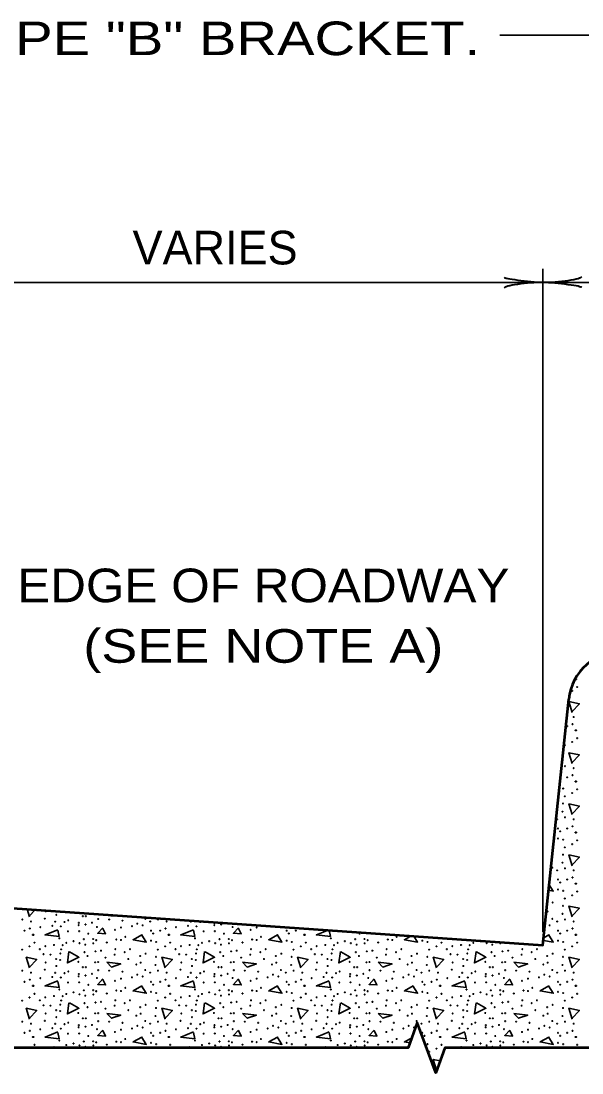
# Model space of a CAD drawing. Extents: x -105 to 751, y -65 to 479.
# Drawn here: x 7.8 to 57.8, y -3.9 to 90 of the extents above; entities that cross this region are included whole.
import ezdxf
from ezdxf.enums import TextEntityAlignment as Align

# ---------------------------------------------------------------- set-up
doc = ezdxf.new("R2010")
doc.units = 0
doc.header["$LTSCALE"] = 1.2
doc.layers.add('1', color=7, linetype='Continuous', lineweight=35)

msp = doc.modelspace()

# ---------------------------------------------------------------- linework, layer by layer
at = {"layer": '1'}
for p, q in [((54.365, 8.704), (54.365, 67.839)), ((8.582, 10.032), (8.375, 10.72)), ((9.108, 10.669), (8.558, 10.08)), ((54.902, 8.424), (54.435, 8.169)), ((44.957, -3.481), (44.846, -3.6))]:
    msp.add_line(p, q, dxfattribs=at)
for points in [[(50.512, 88.687), (79.059, 88.687), (79.059, 72.823)], [(-1.897, 66.639), (54.365, 66.639), (105.725, 66.639)], [(56.966, 28.272), (56.678, 29.232), (57.614, 29.04), (56.942, 28.32)], [(56.966, 23.712), (56.678, 24.672), (57.614, 24.48), (56.942, 23.76)], [(56.966, 19.152), (56.678, 20.112), (57.614, 19.92), (56.942, 19.2)], [(56.966, 14.592), (56.678, 15.552), (57.614, 15.36), (56.942, 14.64)], [(54.881, 12.41), (55.286, 12.336), (54.931, 12.888)], [(56.966, 10.032), (56.678, 10.992), (57.614, 10.8), (56.942, 10.08)], [(16.116, 10.179), (15.902, 10.104), (15.805, 10.201)], [(11.102, 8.88), (9.974, 8.424), (11.222, 8.28), (11.102, 8.832)], [(15.134, 9.048), (14.678, 8.568), (15.374, 8.52), (15.134, 9)], [(18.614, 8.424), (17.822, 7.992), (18.998, 7.776), (18.566, 8.448)], [(23.198, 8.88), (22.07, 8.424), (23.318, 8.28), (23.198, 8.832)], [(27.23, 9.048), (26.774, 8.568), (27.47, 8.52), (27.23, 9)], [(30.71, 8.424), (29.918, 7.992), (31.094, 7.776), (30.662, 8.448)], [(35.206, 8.844), (34.166, 8.424), (35.414, 8.28), (35.294, 8.832)], [(38.888, 8.587), (38.87, 8.568), (39.566, 8.52), (39.556, 8.54)], [(54.411, 7.936), (55.286, 7.776), (54.854, 8.448)], [(42.626, 8.325), (42.014, 7.992), (43.19, 7.776), (42.846, 8.31)], [(12.158, 6.912), (12.998, 6.432), (11.966, 5.928), (12.11, 6.936)], [(24.254, 6.912), (25.094, 6.432), (24.062, 5.928), (24.206, 6.936)], [(36.35, 6.912), (37.19, 6.432), (36.158, 5.928), (36.302, 6.936)], [(48.446, 6.912), (49.286, 6.432), (48.254, 5.928), (48.398, 6.936)], [(8.582, 5.472), (8.294, 6.432), (9.23, 6.24), (8.558, 5.52)], [(20.678, 5.472), (20.39, 6.432), (21.326, 6.24), (20.654, 5.52)], [(32.774, 5.472), (32.486, 6.432), (33.422, 6.24), (32.75, 5.52)], [(44.87, 5.472), (44.582, 6.432), (45.518, 6.24), (44.846, 5.52)], [(56.966, 5.472), (56.678, 6.432), (57.614, 6.24), (56.942, 5.52)], [(11.102, 4.32), (9.974, 3.864), (11.222, 3.72), (11.102, 4.272)], [(15.134, 4.488), (14.678, 4.008), (15.374, 3.96), (15.134, 4.44)], [(18.614, 3.864), (17.822, 3.432), (18.998, 3.216), (18.566, 3.888)], [(23.198, 4.32), (22.07, 3.864), (23.318, 3.72), (23.198, 4.272)], [(27.23, 4.488), (26.774, 4.008), (27.47, 3.96), (27.23, 4.44)], [(30.71, 3.864), (29.918, 3.432), (31.094, 3.216), (30.662, 3.888)], [(35.294, 4.32), (34.166, 3.864), (35.414, 3.72), (35.294, 4.272)], [(39.326, 4.488), (38.87, 4.008), (39.566, 3.96), (39.326, 4.44)], [(42.806, 3.864), (42.014, 3.432), (43.19, 3.216), (42.758, 3.888)], [(47.39, 4.32), (46.262, 3.864), (47.51, 3.72), (47.39, 4.272)], [(51.422, 4.488), (50.966, 4.008), (51.662, 3.96), (51.422, 4.44)], [(54.902, 3.864), (54.11, 3.432), (55.286, 3.216), (54.854, 3.888)], [(12.158, 2.352), (12.998, 1.872), (11.966, 1.368), (12.11, 2.376)], [(24.254, 2.352), (25.094, 1.872), (24.062, 1.368), (24.206, 2.376)], [(36.35, 2.352), (37.19, 1.872), (36.158, 1.368), (36.302, 2.376)], [(48.446, 2.352), (49.286, 1.872), (48.254, 1.368), (48.398, 2.376)], [(8.582, 0.912), (8.294, 1.872), (9.23, 1.68), (8.558, 0.96)], [(20.678, 0.912), (20.39, 1.872), (21.326, 1.68), (20.654, 0.96)], [(32.774, 0.912), (32.486, 1.872), (33.422, 1.68), (32.75, 0.96)], [(44.87, 0.912), (44.582, 1.872), (45.518, 1.68), (44.846, 0.96)], [(56.966, 0.912), (56.678, 1.872), (57.614, 1.68), (56.942, 0.96)], [(11.102, -0.24), (9.974, -0.696), (11.222, -0.84), (11.102, -0.288)], [(15.134, -0.072), (14.678, -0.552), (15.374, -0.6), (15.134, -0.12)], [(18.614, -0.696), (17.822, -1.128), (18.998, -1.344), (18.566, -0.672)], [(23.198, -0.24), (22.07, -0.696), (23.318, -0.84), (23.198, -0.288)], [(27.23, -0.072), (26.774, -0.552), (27.47, -0.6), (27.23, -0.12)], [(30.71, -0.696), (29.918, -1.128), (31.094, -1.344), (30.662, -0.672)], [(35.294, -0.24), (34.166, -0.696), (35.414, -0.84), (35.294, -0.288)], [(39.326, -0.072), (38.87, -0.552), (39.566, -0.6), (39.326, -0.12)], [(42.658, -0.777), (42.014, -1.128), (42.498, -1.217)], [(47.39, -0.24), (46.262, -0.696), (47.51, -0.84), (47.39, -0.288)], [(51.422, -0.072), (50.966, -0.552), (51.662, -0.6), (51.422, -0.12)], [(54.902, -0.696), (54.11, -1.128), (55.286, -1.344), (54.854, -0.672)], [(44.87, -3.648), (44.582, -2.688), (45.2, -2.815)]]:
    msp.add_lwpolyline(points, dxfattribs=at)
at = {"layer": '1', "lineweight": 53}
for points in [[(-24.539, 11.439), (-1.897, 11.439), (54.365, 7.504), (56.673, 29.462)], [(120.627, -1.64), (45.627, -1.64), (44.806, -3.895), (43.165, 0.615), (42.344, -1.64), (-3.856, -1.64), (-4.677, -3.895), (-6.318, 0.615), (-7.139, -1.64), (-24.539, -1.64), (-24.539, 3.258), (-26.794, 4.079), (-22.284, 5.72), (-24.539, 6.541), (-24.539, 11.439)]]:
    msp.add_lwpolyline(points, dxfattribs=at)
at = {"layer": '1'}
for points in [[(15.47, 5.976), (16.718, 5.832), (15.902, 5.544)], [(27.566, 5.976), (28.814, 5.832), (27.998, 5.544)], [(39.662, 5.976), (40.91, 5.832), (40.094, 5.544)], [(51.758, 5.976), (53.006, 5.832), (52.19, 5.544)], [(15.47, 1.416), (16.718, 1.272), (15.902, 0.984)], [(27.566, 1.416), (28.814, 1.272), (27.998, 0.984)], [(39.662, 1.416), (40.91, 1.272), (40.094, 0.984)], [(51.758, 1.416), (53.006, 1.272), (52.19, 0.984)]]:
    msp.add_lwpolyline(points, close=True, dxfattribs=at)
for centre in [(57.334, 31.232), (56.968, 30.198), (57.413, 30.532), (57, 27.229), (57.111, 27.86), (56.523, 27.038), (57.27, 26.672), (57.334, 26.672), (56.316, 25.352), (56.968, 25.638), (57.413, 25.972), (56.332, 23.475), (57, 22.669), (57.111, 23.3), (56.523, 22.478), (57.27, 22.112), (57.334, 22.112), (56.173, 21.476), (56.316, 20.792), (56.968, 21.078), (57.413, 21.412), (56.157, 20.14), (55.632, 18.74), (56.109, 19.424), (56.332, 18.915), (57.111, 18.74), (55.711, 17.918), (56.523, 17.918), (57, 18.109), (55.711, 17.027), (55.902, 17.664), (56.173, 16.916), (57.27, 17.552), (57.334, 17.552), (56.316, 16.232), (56.968, 16.518), (57.413, 16.852), (56.157, 15.58), (55.203, 14.418), (55.632, 14.18), (56.109, 14.864), (56.332, 14.355), (57.111, 14.18), (55.711, 13.358), (56.523, 13.358), (57, 13.549), (55.711, 12.467), (55.902, 13.104), (56.173, 12.356), (57.27, 12.992), (57.334, 12.992), (57.413, 12.292), (55.234, 11.306), (56.316, 11.672), (56.968, 11.958), (10.031, 10.526), (54.789, 10.511), (56.109, 10.304), (56.157, 11.02), (7.948, 9.795), (8.727, 9.62), (9.952, 9.874), (10.874, 9.604), (10.985, 10.208), (11.717, 9.572), (12.051, 9.715), (12.989, 9.492), (13.339, 10.097), (13.578, 9.355), (13.609, 10.097), (14.166, 9.508), (14.716, 9.842), (15.686, 9.795), (16.879, 9.699), (18.199, 9.429), (18.915, 9.858), (19.344, 9.62), (20.044, 9.795), (20.823, 9.62), (22.97, 9.604), (23.813, 9.572), (25.085, 9.492), (25.674, 9.355), (55.203, 9.858), (55.632, 9.62), (56.332, 9.795), (57.111, 9.62), (8.139, 8.798), (8.616, 8.989), (8.886, 8.432), (8.95, 8.432), (9.554, 9.116), (10.62, 9.228), (11.383, 9.18), (12.019, 8.735), (12.973, 9.291), (13.021, 8.75), (13.832, 8.528), (14.605, 9.132), (16.211, 8.878), (16.752, 9.084), (17.722, 9.196), (18.676, 9.275), (19.423, 8.798), (19.614, 8.544), (20.235, 8.798), (20.712, 8.989), (20.982, 8.432), (21.046, 8.432), (21.65, 9.116), (22.716, 9.228), (23.479, 9.18), (24.115, 8.735), (25.069, 9.291), (25.117, 8.75), (25.928, 8.528), (26.701, 9.132), (28.307, 8.878), (28.848, 9.084), (31.519, 8.798), (31.71, 8.544), (32.331, 8.798), (33.078, 8.432), (33.142, 8.432), (36.211, 8.735), (38.024, 8.528), (54.964, 9.275), (55.711, 8.798), (55.902, 8.544), (56.523, 8.798), (57, 8.989), (57.27, 8.432), (57.334, 8.432), (9.029, 7.732), (10.779, 7.526), (11.256, 8.114), (11.542, 7.51), (11.876, 7.716), (12.512, 7.86), (13.053, 7.685), (13.434, 8.035), (13.562, 7.557), (14.262, 8.05), (14.277, 7.669), (14.541, 7.955), (15.479, 7.748), (16.338, 8.019), (16.752, 7.971), (17.133, 8.257), (19.423, 7.907), (19.885, 7.796), (21.125, 7.732), (22.875, 7.526), (23.352, 8.114), (23.638, 7.51), (23.972, 7.716), (24.608, 7.86), (25.149, 7.685), (25.53, 8.035), (25.658, 7.557), (26.358, 8.05), (26.373, 7.669), (26.637, 7.955), (27.575, 7.748), (28.434, 8.019), (28.848, 7.971), (29.229, 8.257), (31.519, 7.907), (31.981, 7.796), (33.221, 7.732), (34.971, 7.526), (35.448, 8.114), (35.734, 7.51), (36.068, 7.716), (36.704, 7.86), (37.245, 7.685), (37.626, 8.035), (37.754, 7.557), (38.454, 8.05), (38.469, 7.669), (38.733, 7.955), (39.671, 7.748), (40.53, 8.019), (40.944, 7.971), (41.325, 8.257), (43.615, 7.907), (44.077, 7.796), (45.317, 7.732), (47.067, 7.526), (47.83, 7.51), (48.164, 7.716), (48.8, 7.86), (49.341, 7.685), (49.85, 7.557), (50.565, 7.669), (55.711, 7.907), (56.173, 7.796), (57.413, 7.732), (7.932, 7.112), (8.584, 7.398), (9.506, 7.144), (9.84, 6.698), (9.999, 7.414), (10.46, 6.666), (11.335, 6.762), (11.415, 7.128), (13.498, 6.889), (13.768, 6.539), (14.468, 6.953), (14.97, 7.016), (16.179, 6.666), (16.243, 7.144), (17.07, 6.889), (17.547, 7.144), (18.453, 6.539), (18.946, 6.746), (20.028, 7.112), (20.68, 7.398), (21.602, 7.144), (21.936, 6.698), (22.095, 7.414), (22.556, 6.666), (23.431, 6.762), (23.511, 7.128), (25.594, 6.889), (25.864, 6.539), (26.564, 6.953), (27.066, 7.016), (28.275, 6.666), (28.339, 7.144), (29.166, 6.889), (29.643, 7.144), (30.549, 6.539), (31.042, 6.746), (32.124, 7.112), (32.776, 7.398), (33.698, 7.144), (34.032, 6.698), (34.191, 7.414), (34.652, 6.666), (35.527, 6.762), (35.607, 7.128), (37.69, 6.889), (37.96, 6.539), (38.66, 6.953), (39.162, 7.016), (40.371, 6.666), (40.435, 7.144), (41.262, 6.889), (41.739, 7.144), (42.645, 6.539), (43.138, 6.746), (44.22, 7.112), (44.872, 7.398), (45.794, 7.144), (46.128, 6.698), (46.287, 7.414), (46.748, 6.666), (47.623, 6.762), (47.703, 7.128), (49.786, 6.889), (50.056, 6.539), (50.756, 6.953), (51.258, 7.016), (52.467, 6.666), (52.531, 7.144), (53.358, 6.889), (53.835, 7.144), (54.741, 6.539), (55.234, 6.746), (56.316, 7.112), (56.968, 7.398), (10.031, 5.966), (10.969, 6.269), (10.985, 5.648), (11.319, 6.189), (12.941, 6.014), (14.445, 5.98), (14.716, 5.998), (15.368, 6.396), (17.404, 6.269), (18.119, 5.776), (18.501, 5.951), (19.821, 5.744), (19.869, 6.46), (22.127, 5.966), (23.065, 6.269), (23.081, 5.648), (23.415, 6.189), (25.037, 6.014), (26.541, 5.98), (26.812, 5.998), (27.464, 6.396), (29.5, 6.269), (30.215, 5.776), (30.597, 5.951), (31.917, 5.744), (31.965, 6.46), (34.223, 5.966), (35.161, 6.269), (35.177, 5.648), (35.511, 6.189), (37.133, 6.014), (38.637, 5.98), (38.908, 5.998), (39.56, 6.396), (41.596, 6.269), (42.311, 5.776), (42.693, 5.951), (44.013, 5.744), (44.061, 6.46), (46.319, 5.966), (47.257, 6.269), (47.273, 5.648), (47.607, 6.189), (49.229, 6.014), (50.733, 5.98), (51.004, 5.998), (51.656, 6.396), (53.692, 6.269), (54.407, 5.776), (54.789, 5.951), (56.109, 5.744), (56.157, 6.46), (7.948, 5.235), (8.727, 5.06), (9.952, 5.314), (10.62, 4.668), (10.874, 5.044), (11.717, 5.012), (12.051, 5.155), (12.973, 4.731), (12.989, 4.932), (13.339, 5.537), (13.578, 4.795), (13.609, 5.537), (14.166, 4.948), (14.716, 5.282), (15.686, 5.235), (16.879, 5.139), (18.199, 4.869), (18.676, 4.715), (18.915, 5.298), (19.344, 5.06), (20.044, 5.235), (20.823, 5.06), (22.048, 5.314), (22.716, 4.668), (22.97, 5.044), (23.813, 5.012), (24.147, 5.155), (25.069, 4.731), (25.085, 4.932), (25.435, 5.537), (25.674, 4.795), (25.705, 5.537), (26.262, 4.948), (26.812, 5.282), (27.782, 5.235), (28.975, 5.139), (30.295, 4.869), (30.772, 4.715), (31.011, 5.298), (31.44, 5.06), (32.14, 5.235), (32.919, 5.06), (34.144, 5.314), (34.812, 4.668), (35.066, 5.044), (35.909, 5.012), (36.243, 5.155), (37.165, 4.731), (37.181, 4.932), (37.531, 5.537), (37.77, 4.795), (37.801, 5.537), (38.358, 4.948), (38.908, 5.282), (39.878, 5.235), (41.071, 5.139), (42.391, 4.869), (42.868, 4.715), (43.107, 5.298), (43.536, 5.06), (44.236, 5.235), (45.015, 5.06), (46.24, 5.314), (46.908, 4.668), (47.162, 5.044), (48.005, 5.012), (48.339, 5.155), (49.261, 4.731), (49.277, 4.932), (49.627, 5.537), (49.866, 4.795), (49.897, 5.537), (50.454, 4.948), (51.004, 5.282), (51.974, 5.235), (53.167, 5.139), (54.487, 4.869), (54.964, 4.715), (55.203, 5.298), (55.632, 5.06), (56.332, 5.235), (57.111, 5.06), (8.139, 4.238), (8.616, 4.429), (8.886, 3.872), (8.95, 3.872), (9.554, 4.556), (11.383, 4.62), (12.019, 4.175), (13.021, 4.19), (13.832, 3.968), (14.605, 4.572), (16.211, 4.318), (16.752, 4.524), (17.722, 4.636), (19.423, 4.238), (19.614, 3.984), (20.235, 4.238), (20.712, 4.429), (20.982, 3.872), (21.046, 3.872), (21.65, 4.556), (23.479, 4.62), (24.115, 4.175), (25.117, 4.19), (25.928, 3.968), (26.701, 4.572), (28.307, 4.318), (28.848, 4.524), (29.818, 4.636), (31.519, 4.238), (31.71, 3.984), (32.331, 4.238), (32.808, 4.429), (33.078, 3.872), (33.142, 3.872), (33.746, 4.556), (35.575, 4.62), (36.211, 4.175), (37.213, 4.19), (38.024, 3.968), (38.797, 4.572), (40.403, 4.318), (40.944, 4.524), (41.914, 4.636), (43.615, 4.238), (43.806, 3.984), (44.427, 4.238), (44.904, 4.429), (45.174, 3.872), (45.238, 3.872), (45.842, 4.556), (47.671, 4.62), (48.307, 4.175), (49.309, 4.19), (50.12, 3.968), (50.893, 4.572), (52.499, 4.318), (53.04, 4.524), (54.01, 4.636), (55.711, 4.238), (55.902, 3.984), (56.523, 4.238), (57, 4.429), (57.27, 3.872), (57.334, 3.872), (8.584, 2.838), (9.029, 3.172), (9.999, 2.854), (10.779, 2.966), (11.256, 3.554), (11.542, 2.95), (11.876, 3.156), (12.512, 3.3), (13.053, 3.125), (13.434, 3.475), (13.562, 2.997), (14.262, 3.49), (14.277, 3.109), (14.541, 3.395), (15.479, 3.188), (16.338, 3.459), (16.752, 3.411), (17.133, 3.697), (19.423, 3.347), (19.885, 3.236), (20.68, 2.838), (21.125, 3.172), (22.095, 2.854), (22.875, 2.966), (23.352, 3.554), (23.638, 2.95), (23.972, 3.156), (24.608, 3.3), (25.149, 3.125), (25.53, 3.475), (25.658, 2.997), (26.358, 3.49), (26.373, 3.109), (26.637, 3.395), (27.575, 3.188), (28.434, 3.459), (28.848, 3.411), (29.229, 3.697), (31.519, 3.347), (31.981, 3.236), (32.776, 2.838), (33.221, 3.172), (34.191, 2.854), (34.971, 2.966), (35.448, 3.554), (35.734, 2.95), (36.068, 3.156), (36.704, 3.3), (37.245, 3.125), (37.626, 3.475), (37.754, 2.997), (38.454, 3.49), (38.469, 3.109), (38.733, 3.395), (39.671, 3.188), (40.53, 3.459), (40.944, 3.411), (41.325, 3.697), (43.615, 3.347), (44.077, 3.236), (44.872, 2.838), (45.317, 3.172), (46.287, 2.854), (47.067, 2.966), (47.544, 3.554), (47.83, 2.95), (48.164, 3.156), (48.8, 3.3), (49.341, 3.125), (49.722, 3.475), (49.85, 2.997), (50.55, 3.49), (50.565, 3.109), (50.829, 3.395), (51.767, 3.188), (52.626, 3.459), (53.04, 3.411), (53.421, 3.697), (55.711, 3.347), (56.173, 3.236), (56.968, 2.838), (57.413, 3.172), (7.932, 2.552), (9.506, 2.584), (9.84, 2.138), (10.46, 2.106), (11.335, 2.202), (11.415, 2.568), (13.498, 2.329), (13.768, 1.979), (14.468, 2.393), (14.97, 2.456), (16.179, 2.106), (16.243, 2.584), (17.07, 2.329), (17.547, 2.584), (18.453, 1.979), (18.946, 2.186), (19.869, 1.9), (20.028, 2.552), (21.602, 2.584), (21.936, 2.138), (22.556, 2.106), (23.431, 2.202), (23.511, 2.568), (25.594, 2.329), (25.864, 1.979), (26.564, 2.393), (27.066, 2.456), (28.275, 2.106), (28.339, 2.584), (29.166, 2.329), (29.643, 2.584), (30.549, 1.979), (31.042, 2.186), (31.965, 1.9), (32.124, 2.552), (33.698, 2.584), (34.032, 2.138), (34.652, 2.106), (35.527, 2.202), (35.607, 2.568), (37.69, 2.329), (37.96, 1.979), (38.66, 2.393), (39.162, 2.456), (40.371, 2.106), (40.435, 2.584), (41.262, 2.329), (41.739, 2.584), (42.645, 1.979), (43.138, 2.186), (44.061, 1.9), (44.22, 2.552), (45.794, 2.584), (46.128, 2.138), (46.748, 2.106), (47.623, 2.202), (47.703, 2.568), (49.786, 2.329), (50.056, 1.979), (50.756, 2.393), (51.258, 2.456), (52.467, 2.106), (52.531, 2.584), (53.358, 2.329), (53.835, 2.584), (54.741, 1.979), (55.234, 2.186), (56.157, 1.9), (56.316, 2.552), (10.031, 1.406), (10.969, 1.709), (10.985, 1.088), (11.319, 1.629), (12.941, 1.454), (13.339, 0.977), (13.609, 0.977), (14.445, 1.42), (14.716, 1.438), (15.368, 1.836), (17.404, 1.709), (18.119, 1.216), (18.501, 1.391), (19.821, 1.184), (22.127, 1.406), (23.065, 1.709), (23.081, 1.088), (23.415, 1.629), (25.037, 1.454), (25.435, 0.977), (25.705, 0.977), (26.541, 1.42), (26.812, 1.438), (27.464, 1.836), (29.5, 1.709), (30.215, 1.216), (30.597, 1.391), (31.917, 1.184), (34.223, 1.406), (35.161, 1.709), (35.177, 1.088), (35.511, 1.629), (37.133, 1.454), (37.531, 0.977), (37.801, 0.977), (38.637, 1.42), (38.908, 1.438), (39.56, 1.836), (41.596, 1.709), (42.311, 1.216), (42.693, 1.391), (44.013, 1.184), (46.319, 1.406), (47.257, 1.709), (47.273, 1.088), (47.607, 1.629), (49.229, 1.454), (49.627, 0.977), (49.897, 0.977), (50.733, 1.42), (51.004, 1.438), (51.656, 1.836), (53.692, 1.709), (54.407, 1.216), (54.789, 1.391), (56.109, 1.184), (7.948, 0.675), (8.727, 0.5), (9.554, -0.004), (9.952, 0.754), (10.62, 0.108), (10.874, 0.484), (11.383, 0.06), (11.717, 0.452), (12.051, 0.595), (12.973, 0.171), (12.989, 0.372), (13.578, 0.235), (14.166, 0.388), (14.605, 0.012), (14.716, 0.722), (15.686, 0.675), (16.879, 0.579), (17.722, 0.076), (18.199, 0.309), (18.676, 0.155), (18.915, 0.738), (19.344, 0.5), (20.044, 0.675), (20.823, 0.5), (21.65, -0.004), (22.048, 0.754), (22.716, 0.108), (22.97, 0.484), (23.479, 0.06), (23.813, 0.452), (24.147, 0.595), (25.069, 0.171), (25.085, 0.372), (25.674, 0.235), (26.262, 0.388), (26.701, 0.012), (26.812, 0.722), (27.782, 0.675), (28.975, 0.579), (29.818, 0.076), (30.295, 0.309), (30.772, 0.155), (31.011, 0.738), (31.44, 0.5), (32.14, 0.675), (32.919, 0.5), (33.746, -0.004), (34.144, 0.754), (34.812, 0.108), (35.066, 0.484), (35.575, 0.06), (35.909, 0.452), (36.243, 0.595), (37.165, 0.171), (37.181, 0.372), (37.77, 0.235), (38.358, 0.388), (38.797, 0.012), (38.908, 0.722), (39.878, 0.675), (41.071, 0.579), (41.914, 0.076), (42.391, 0.309), (42.868, 0.155), (43.107, 0.738), (43.536, 0.5), (44.236, 0.675), (45.015, 0.5), (45.842, -0.004), (46.24, 0.754), (46.908, 0.108), (47.162, 0.484), (47.671, 0.06), (48.005, 0.452), (48.339, 0.595), (49.261, 0.171), (49.277, 0.372), (49.866, 0.235), (50.454, 0.388), (50.893, 0.012), (51.004, 0.722), (51.974, 0.675), (53.167, 0.579), (54.01, 0.076), (54.487, 0.309), (54.964, 0.155), (55.203, 0.738), (55.632, 0.5), (56.332, 0.675), (57.111, 0.5), (8.139, -0.322), (8.616, -0.131), (8.886, -0.688), (8.95, -0.688), (12.019, -0.385), (13.021, -0.37), (13.832, -0.592), (16.211, -0.242), (16.752, -0.036), (17.133, -0.863), (19.423, -0.322), (19.614, -0.576), (20.235, -0.322), (20.712, -0.131), (20.982, -0.688), (21.046, -0.688), (24.115, -0.385), (25.117, -0.37), (25.928, -0.592), (28.307, -0.242), (28.848, -0.036), (29.229, -0.863), (31.519, -0.322), (31.71, -0.576), (32.331, -0.322), (32.808, -0.131), (33.078, -0.688), (33.142, -0.688), (36.211, -0.385), (37.213, -0.37), (38.024, -0.592), (40.403, -0.242), (40.944, -0.036), (41.325, -0.863), (43.615, -0.322), (43.806, -0.576), (44.427, -0.322), (44.904, -0.131), (45.174, -0.688), (45.238, -0.688), (48.307, -0.385), (49.309, -0.37), (50.12, -0.592), (52.499, -0.242), (53.04, -0.036), (53.421, -0.863), (55.711, -0.322), (55.902, -0.576), (56.523, -0.322), (57, -0.131), (57.27, -0.688), (57.334, -0.688), (9.029, -1.388), (10.779, -1.594), (11.256, -1.006), (11.876, -1.404), (12.512, -1.26), (13.053, -1.435), (13.434, -1.085), (13.562, -1.563), (14.262, -1.07), (14.277, -1.451), (14.541, -1.165), (15.479, -1.372), (16.338, -1.101), (16.752, -1.149), (19.423, -1.213), (19.885, -1.324), (21.125, -1.388), (22.875, -1.594), (23.352, -1.006), (23.972, -1.404), (24.608, -1.26), (25.149, -1.435), (25.53, -1.085), (25.658, -1.563), (26.358, -1.07), (26.373, -1.451), (26.637, -1.165), (27.575, -1.372), (28.434, -1.101), (28.848, -1.149), (31.519, -1.213), (31.981, -1.324), (33.221, -1.388), (34.971, -1.594), (35.448, -1.006), (36.068, -1.404), (36.704, -1.26), (37.245, -1.435), (37.626, -1.085), (37.754, -1.563), (38.454, -1.07), (38.469, -1.451), (38.733, -1.165), (39.671, -1.372), (40.53, -1.101), (40.944, -1.149), (44.077, -1.324), (44.872, -1.722), (45.317, -1.388), (47.067, -1.594), (47.544, -1.006), (48.164, -1.404), (48.8, -1.26), (49.341, -1.435), (49.722, -1.085), (49.85, -1.563), (50.55, -1.07), (50.565, -1.451), (50.829, -1.165), (51.767, -1.372), (52.626, -1.101), (53.04, -1.149), (55.711, -1.213), (56.173, -1.324), (57.413, -1.388), (44.22, -2.008)]:
    msp.add_circle(centre, 0.0318, dxfattribs=at)
at = {"layer": '1', "lineweight": 53}
msp.add_arc((61.447, 28.96), 4.8, 90, 173.99999, dxfattribs=at)
at = {"layer": '1'}
for centre, start, end in [((57.27, 31.232), 266.69977, 55.52014), ((56.157, 24.7), 293.84707, 54.15285), ((56.109, 23.984), 242.55118, 105.44874), ((55.902, 22.224), 282.39136, 65.60856), ((55.234, 15.866), 281.97443, 66.02548), ((54.741, 11.099), 267.31563, 80.68429), ((29.818, 9.196), 124.01985, 47.98008), ((32.808, 8.989), 130.40887, 41.59105), ((11.542, -1.61), 290.25809, 249.74191), ((23.638, -1.61), 290.25809, 249.74191), ((35.734, -1.61), 290.25809, 249.74191), ((47.83, -1.61), 290.25809, 249.74191)]:
    msp.add_arc(centre, 0.0318, start, end, dxfattribs=at)
at = {"layer": '1', "lineweight": 40}
for centre, major_axis, ratio, start_param, end_param in [((53.056, 66.307), (2.143, 0.187), 0.122415, 0.896353, 3.141593), ((53.056, 66.307), (2.143, 0.187), 0.122415, 0.896353, 3.141593), ((53.021, 66.893), (2.108, -0.211), 0.07063, 3.140715, 5.41811), ((53.021, 66.893), (2.108, -0.211), 0.07063, 3.140715, 5.41811), ((55.71, 66.385), (-2.108, 0.211), 0.07063, 3.140715, 5.41811), ((55.71, 66.385), (-2.108, 0.211), 0.07063, 3.140715, 5.41811), ((55.675, 66.97), (-2.143, -0.187), 0.122415, 0.896353, 3.141593), ((55.675, 66.97), (-2.143, -0.187), 0.122415, 0.896353, 3.141593)]:
    msp.add_ellipse(centre, major_axis=major_axis, ratio=ratio, start_param=start_param, end_param=end_param, dxfattribs=at)

# ---------------------------------------------------------------- texts
at = {"layer": '1', "width": 1.25}
msp.add_text('ITS TYPE "B" BRACKET. ', height=3, dxfattribs=at).set_placement((-8.291, 86.909))
at = {"layer": '1'}
msp.add_text('VARIES', height=3, dxfattribs=at).set_placement((17.777, 68.24))
for s, width, p in [('EDGE OF ROADWAY', 1.1, (29.435, 38.101)), ('(SEE NOTE A)', 1.2, (29.435, 32.701))]:
    msp.add_text(s, height=3, dxfattribs=dict(at, width=width)).set_placement(p, align=Align.CENTER)

doc.saveas('drawing.dxf')
